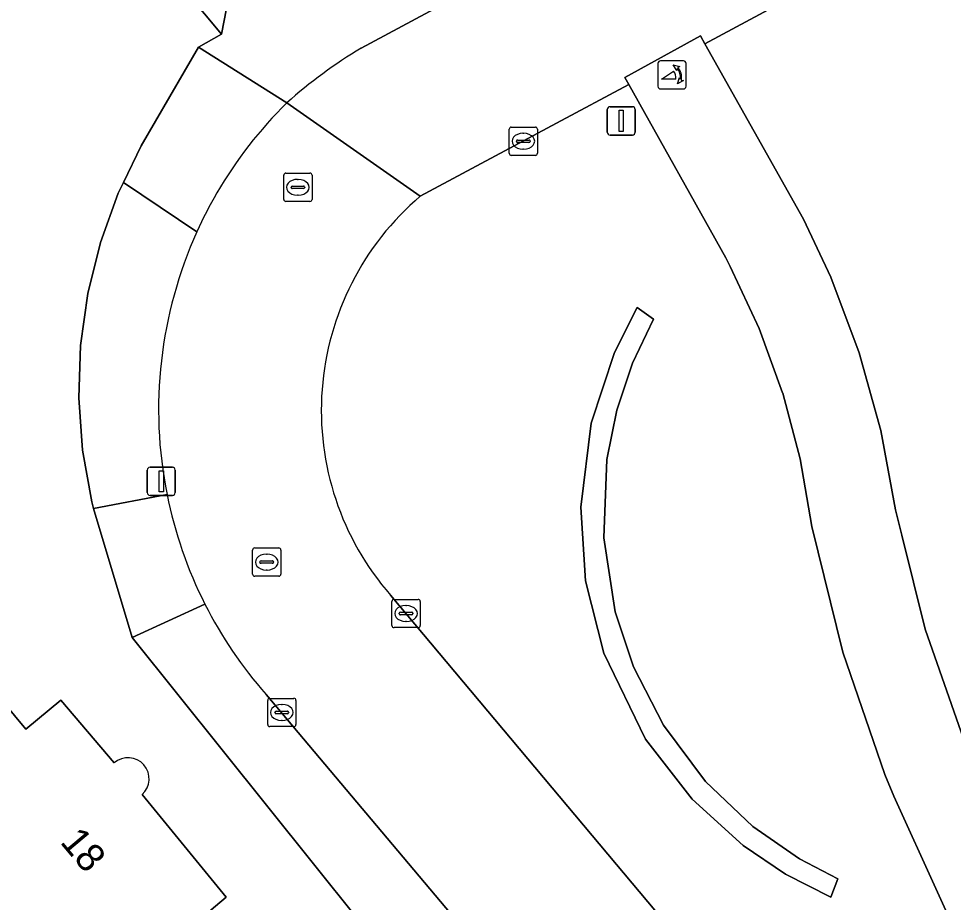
# Model space of a CAD drawing. Extents: x 157320 to 158835, y 386650 to 388491.
# Drawn here: x 157959.22 to 157992.29, y 387030.42 to 387061.67 of the extents above; entities that cross this region are included whole.
import ezdxf

# ---------------------------------------------------------------- set-up
doc = ezdxf.new("R2010")
doc.units = 0
for name, color, linetype in [('IMGEO_Erf', 7, 'Continuous'), ('IMGEO_Fietspad_gesloten', 7, 'Continuous'), ('IMGEO_Groenvoorziening', 7, 'Continuous'), ('IMGEO_Kolk', 7, 'Continuous'), ('IMGEO_Lichtmast', 7, 'Continuous'), ('IMGEO_Pand', 7, 'Continuous'), ('IMGEO_Pand_nummerreeks', 7, 'Continuous'), ('IMGEO_Poller', 7, 'Continuous'), ('IMGEO_Rijbaan_lokaal_gesloten', 7, 'Continuous'), ('IMGEO_Rioolput', 7, 'Continuous'), ('IMGEO_Verkeersbordpaal', 7, 'Continuous'), ('IMGEO_Voetpad_open', 7, 'Continuous')]:
    doc.layers.add(name, color=color, linetype=linetype)

msp = doc.modelspace()

# ---------------------------------------------------------------- linework, layer by layer
at = {"layer": 'IMGEO_Erf'}
for points in [[(157991.12, 387006.005), (157981.864, 387017.312), (157978.709, 387020.934), (157976.019, 387024.066), (157974.987, 387025.267), (157972.834, 387027.804), (157963.229, 387039.777), (157961.86, 387044.345), (157961.804, 387044.578), (157961.479, 387046.406), (157961.346, 387048.258), (157961.408, 387050.114), (157961.663, 387051.953), (157962.109, 387053.755), (157962.741, 387055.501), (157962.924, 387055.878), (157963.552, 387057.171), (157965.583, 387060.657), (157966.396, 387061.12), (157947.439, 387083.778)], [(157966.029, 387021.933), (157957.602, 387014.853), (157953.366, 387019.902), (157958.268, 387024.015), (157952.8, 387030.549), (157947.889, 387026.428), (157943.654, 387031.476), (157951.624, 387038.164), (157955.453, 387041.378), (157959.468, 387036.534), (157960.714, 387037.566), (157962.597, 387035.343)], [(157963.583, 387034.226), (157966.563, 387030.599), (157965.801, 387029.956), (157969.857, 387025.149), (157966.029, 387021.933)]]:
    msp.add_lwpolyline(points, dxfattribs=at)
msp.add_arc((157963.088, 387034.783), 0.745, 311.6564, 131.2146, dxfattribs=at)
at = {"layer": 'IMGEO_Fietspad_gesloten'}
msp.add_lwpolyline([(157992.732, 387035.958), (157991.3, 387040.074), (157990.468, 387043.398), (157990.242, 387044.301), (157989.728, 387047.106), (157988.965, 387049.855), (157987.959, 387052.524), (157986.992, 387054.576), (157983.496, 387060.784), (157983.342, 387061.057), (157980.664, 387059.588), (157980.806, 387059.335), (157984.237, 387053.207), (157984.399, 387052.903), (157985.426, 387050.712), (157986.253, 387048.437), (157986.256, 387048.425), (157986.874, 387046.098), (157987.283, 387043.712), (157988.381, 387039.265), (157989.873, 387034.934), (157990.183, 387034.167), (157994.823, 387023.988)], dxfattribs=at)
at = {"layer": 'IMGEO_Groenvoorziening'}
for points in [[(157948.54, 387084.792), (157947.439, 387083.778), (157966.396, 387061.12), (157966.986, 387064.168)], [(157971.339, 387060.631), (157974.572, 387062.367), (157977.902, 387064.165), (157977.841, 387064.281), (157977.503, 387064.848), (157977.116, 387065.382), (157976.683, 387065.88), (157976.446, 387066.118), (157976.209, 387066.35), (157975.97, 387066.58)], [(157991.21, 387064.929), (157983.496, 387060.784), (157986.992, 387054.576), (157987.959, 387052.524), (157988.965, 387049.855), (157989.728, 387047.106), (157990.242, 387044.301), (157990.468, 387043.398), (157991.3, 387040.074), (157992.732, 387035.958), (157992.911, 387035.516), (157997.623, 387025.234), (157999.152, 387021.817), (158000, 387020.216), (158001.965, 387017.034), (158003.372, 387015.092), (158006.85, 387010.839), (158007.452, 387010.131), (158008.114, 387009.48), (158008.832, 387008.89)], [(157966.986, 387064.168), (157966.396, 387061.12), (157965.583, 387060.657), (157968.704, 387058.691)], [(158004.726, 387008.62), (158000, 387014.593), (157999.477, 387015.254), (157998.198, 387017.21), (157996.359, 387020.524), (157994.823, 387023.988), (157990.183, 387034.167), (157989.873, 387034.934), (157988.381, 387039.265), (157987.283, 387043.712), (157986.874, 387046.098), (157986.256, 387048.425), (157986.253, 387048.437), (157985.426, 387050.712), (157984.399, 387052.903), (157984.237, 387053.207), (157980.806, 387059.335), (157978.256, 387057.971), (157973.431, 387055.39)], [(157965.527, 387054.133), (157962.924, 387055.878), (157962.741, 387055.501), (157962.109, 387053.755), (157961.663, 387051.953), (157961.408, 387050.114), (157961.346, 387048.258), (157961.479, 387046.406), (157961.804, 387044.578), (157961.86, 387044.345), (157964.468, 387044.834)], [(157972.38, 387041.273), (158000, 387008.374), (158007.03, 387000), (158030.213, 386972.386), (158034.557, 386967.207)], [(157965.81, 387040.962), (157963.229, 387039.777), (157972.834, 387027.804), (157974.9, 387029.543), (157967.973, 387037.769)]]:
    msp.add_lwpolyline(points, dxfattribs=at)
for points in [[(157987.96, 387030.601), (157988.208, 387031.247), (157986.851, 387031.955), (157985.204, 387033.095), (157983.524, 387034.685), (157982.032, 387036.676), (157980.974, 387038.739), (157980.33, 387040.686), (157979.925, 387043.301), (157980.031, 387046.082), (157980.381, 387047.819), (157980.94, 387049.489), (157981.68, 387051.035), (157981.107, 387051.459), (157980.301, 387049.864), (157979.481, 387047.366), (157979.108, 387044.395), (157979.281, 387041.788), (157979.925, 387039.224), (157981.4, 387036.186), (157983.047, 387034.059), (157984.853, 387032.422), (157986.359, 387031.411)], [(157980.94, 387049.489), (157980.381, 387047.819), (157980.031, 387046.082), (157979.925, 387043.301), (157980.33, 387040.686), (157980.974, 387038.739), (157982.032, 387036.676), (157983.524, 387034.685), (157985.204, 387033.095), (157986.851, 387031.955), (157988.208, 387031.247), (157987.96, 387030.601), (157986.359, 387031.411), (157984.853, 387032.422), (157983.047, 387034.059), (157981.4, 387036.186), (157979.925, 387039.224), (157979.281, 387041.788), (157979.108, 387044.395), (157979.481, 387047.366), (157980.301, 387049.864), (157981.107, 387051.459), (157981.68, 387051.035)]]:
    msp.add_lwpolyline(points, close=True, dxfattribs=at)
for centre, radius, start, end in [((157980.387, 387045.582), 17.559, 121.0158, 131.7084), ((157979.873, 387047.813), 9.946, 130.3719, 221.1126), ((157979.394, 387047.844), 15.226, 155.6043, 191.4016), ((157979.27, 387047.751), 15.075, 206.7653, 221.4636)]:
    msp.add_arc(centre, radius, start, end, dxfattribs=at)
at = {"layer": 'IMGEO_Kolk'}
for p, q in [((157976.651, 387057.834), (157977.503, 387057.834)), ((157976.576, 387056.908), (157976.576, 387057.76)), ((157977.064, 387057.614), (157977.089, 387057.614)), ((157977.577, 387057.76), (157977.577, 387056.908)), ((157976.835, 387057.328), (157976.835, 387057.34)), ((157977.273, 387057.291), (157976.875, 387057.291)), ((157976.878, 387057.377), (157977.276, 387057.377)), ((157977.319, 387057.34), (157977.319, 387057.328)), ((157977.503, 387056.834), (157976.651, 387056.834)), ((157977.087, 387057.054), (157977.062, 387057.054)), ((157972.426, 387040.204), (157972.426, 387041.056)), ((157972.501, 387041.13), (157973.353, 387041.13)), ((157972.914, 387040.91), (157972.939, 387040.91)), ((157973.427, 387041.056), (157973.427, 387040.204)), ((157972.685, 387040.624), (157972.685, 387040.636)), ((157973.123, 387040.587), (157972.725, 387040.587)), ((157972.728, 387040.673), (157973.126, 387040.673)), ((157973.169, 387040.636), (157973.169, 387040.624)), ((157972.937, 387040.35), (157972.912, 387040.35)), ((157973.353, 387040.13), (157972.501, 387040.13)), ((157968.104, 387037.629), (157968.956, 387037.629)), ((157968.029, 387036.703), (157968.029, 387037.555)), ((157968.517, 387037.409), (157968.542, 387037.409)), ((157969.03, 387037.555), (157969.03, 387036.703)), ((157968.288, 387037.123), (157968.288, 387037.135)), ((157968.726, 387037.086), (157968.328, 387037.086)), ((157968.331, 387037.172), (157968.729, 387037.172)), ((157968.772, 387037.135), (157968.772, 387037.123)), ((157968.956, 387036.629), (157968.104, 387036.629)), ((157968.54, 387036.849), (157968.515, 387036.849))]:
    msp.add_line(p, q, dxfattribs=at)
for points in [[(157976.651, 387057.834), (157977.503, 387057.834)], [(157976.576, 387056.908), (157976.576, 387057.76)], [(157977.577, 387057.76), (157977.577, 387056.908)], [(157977.503, 387056.834), (157976.651, 387056.834)], [(157972.426, 387040.204), (157972.426, 387041.056)], [(157972.501, 387041.13), (157973.353, 387041.13)], [(157973.427, 387041.056), (157973.427, 387040.204)], [(157973.353, 387040.13), (157972.501, 387040.13)], [(157968.104, 387037.629), (157968.956, 387037.629)], [(157968.029, 387036.703), (157968.029, 387037.555)], [(157969.03, 387037.555), (157969.03, 387036.703)], [(157968.956, 387036.629), (157968.104, 387036.629)]]:
    msp.add_lwpolyline(points, dxfattribs=at)
for centre, radius, start, end in [((157976.653, 387057.758), 0.0765, 91.552, 178.448), ((157976.653, 387057.758), 0.0765, 91.552, 178.448), ((157977.501, 387057.758), 0.0765, 1.552, 88.448), ((157977.501, 387057.758), 0.0765, 1.552, 88.448), ((157976.875, 387057.337), 0.0403, 85.8775, 175.7526), ((157976.872, 387057.327), 0.0366, 178.938, 274.7102), ((157977.276, 387057.334), 0.043, 264.8664, 352.4533), ((157977.28, 387057.339), 0.0386, 1.7309, 96.639), ((157976.653, 387056.91), 0.0765, 181.552, 268.448), ((157976.653, 387056.91), 0.0765, 181.552, 268.448), ((157977.501, 387056.91), 0.0765, 271.552, 358.448), ((157977.501, 387056.91), 0.0765, 271.552, 358.448), ((157972.503, 387041.054), 0.0765, 91.552, 178.448), ((157972.503, 387041.054), 0.0765, 91.552, 178.448), ((157973.351, 387041.054), 0.0765, 1.552, 88.448), ((157973.351, 387041.054), 0.0765, 1.552, 88.448), ((157972.725, 387040.633), 0.0403, 85.8775, 175.7526), ((157972.722, 387040.623), 0.0366, 178.938, 274.7102), ((157973.126, 387040.63), 0.043, 264.8664, 352.4533), ((157973.13, 387040.635), 0.0386, 1.7309, 96.639), ((157972.503, 387040.206), 0.0765, 181.552, 268.448), ((157972.503, 387040.206), 0.0765, 181.552, 268.448), ((157973.351, 387040.206), 0.0765, 271.552, 358.448), ((157973.351, 387040.206), 0.0765, 271.552, 358.448), ((157968.106, 387037.553), 0.0765, 91.552, 178.448), ((157968.106, 387037.553), 0.0765, 91.552, 178.448), ((157968.954, 387037.553), 0.0765, 1.552, 88.448), ((157968.954, 387037.553), 0.0765, 1.552, 88.448), ((157968.328, 387037.132), 0.0403, 85.8775, 175.7526), ((157968.325, 387037.122), 0.0366, 178.938, 274.7102), ((157968.729, 387037.129), 0.043, 264.8664, 352.4533), ((157968.733, 387037.134), 0.0386, 1.7309, 96.639), ((157968.106, 387036.705), 0.0765, 181.552, 268.448), ((157968.106, 387036.705), 0.0765, 181.552, 268.448), ((157968.954, 387036.705), 0.0765, 271.552, 358.448), ((157968.954, 387036.705), 0.0765, 271.552, 358.448)]:
    msp.add_arc(centre, radius, start, end, dxfattribs=at)
for centre, major_axis, ratio, start_param, end_param in [((157977.063, 387057.334), (-0.387, 0.002), 0.722429, 4.712389, 7.853982), ((157977.088, 387057.334), (-0.39, 0.002), 0.717154, 1.570796, 4.712389), ((157972.913, 387040.63), (-0.387, 0.002), 0.722429, 4.712389, 7.853982), ((157972.938, 387040.63), (-0.39, 0.002), 0.717154, 1.570796, 4.712389), ((157968.516, 387037.129), (-0.387, 0.002), 0.722429, 4.712389, 7.853982), ((157968.541, 387037.129), (-0.39, 0.002), 0.717154, 1.570796, 4.712389)]:
    msp.add_ellipse(centre, major_axis=major_axis, ratio=ratio, start_param=start_param, end_param=end_param, dxfattribs=at)
at = {"layer": 'IMGEO_Lichtmast'}
for p, q in [((157963.767, 387044.905), (157963.767, 387045.705)), ((157963.767, 387045.705), (157963.767, 387044.905)), ((157963.867, 387045.805), (157964.657, 387045.805)), ((157964.657, 387045.805), (157963.867, 387045.805)), ((157964.757, 387045.705), (157964.757, 387044.905)), ((157964.757, 387044.905), (157964.757, 387045.705)), ((157964.657, 387044.805), (157963.867, 387044.805)), ((157963.867, 387044.805), (157964.657, 387044.805))]:
    msp.add_line(p, q, dxfattribs=at)
msp.add_lwpolyline([(157964.187, 387045.68), (157964.337, 387045.68), (157964.337, 387044.93), (157964.187, 387044.93), (157964.187, 387045.68)], dxfattribs=at)
for centre, start, end in [((157963.867, 387045.705), 90, 180), ((157963.867, 387045.705), 90, 180), ((157964.657, 387045.705), 0, 90), ((157964.657, 387045.705), 360, 90), ((157963.867, 387044.905), 180, 270), ((157963.867, 387044.905), 180, 270), ((157964.657, 387044.905), 270, 0), ((157964.657, 387044.905), 270, 0)]:
    msp.add_arc(centre, 0.1, start, end, dxfattribs=at)
at = {"layer": 'IMGEO_Pand'}
msp.add_lwpolyline([(157962.597, 387035.343), (157960.714, 387037.566), (157959.468, 387036.534), (157955.453, 387041.378), (157951.624, 387038.164), (157943.654, 387031.476), (157947.889, 387026.428), (157952.8, 387030.549), (157958.268, 387024.015), (157953.366, 387019.902), (157957.602, 387014.853), (157966.029, 387021.933), (157969.857, 387025.149), (157965.801, 387029.956), (157966.563, 387030.599), (157963.583, 387034.226)], dxfattribs=at)
msp.add_arc((157963.088, 387034.783), 0.745, 311.6564, 131.2146, dxfattribs=at)
at = {"layer": 'IMGEO_Poller'}
for p, q in [((157982.742, 387060.179), (157981.934, 387060.179)), ((157982.742, 387060.179), (157981.934, 387060.179)), ((157981.84, 387060.084), (157981.84, 387059.277)), ((157981.84, 387060.084), (157981.84, 387059.277)), ((157982.836, 387059.277), (157982.836, 387060.084)), ((157982.836, 387059.277), (157982.836, 387060.084)), ((157981.934, 387059.182), (157982.742, 387059.182)), ((157981.934, 387059.182), (157982.742, 387059.182))]:
    msp.add_line(p, q, dxfattribs=at)
for points in [[(157982.475, 387059.535), (157981.962, 387059.535), (157982.392, 387059.81)], [(157982.519, 387059.908), (157982.507, 387059.835), (157982.382, 387060.04)], [(157982.382, 387060.04), (157982.613, 387059.974), (157982.542, 387059.942)], [(157982.535, 387059.363), (157982.601, 387059.594), (157982.631, 387059.526)], [(157982.667, 387059.499), (157982.739, 387059.488), (157982.535, 387059.363)]]:
    msp.add_lwpolyline(points, dxfattribs=at)
for centre, radius, start, end in [((157981.934, 387060.084), 0.0946, 90, 180), ((157981.934, 387060.084), 0.0946, 90, 180), ((157982.742, 387060.084), 0.0946, 0, 90), ((157982.742, 387060.084), 0.0946, 0, 90), ((157982.147, 387059.585), 0.332, 351.3247, 42.4854), ((157982.161, 387059.595), 0.476, 351.7527, 41.1691), ((157982.161, 387059.595), 0.516, 349.3569, 42.2912), ((157981.934, 387059.277), 0.0946, 180, 270), ((157981.934, 387059.277), 0.0946, 180, 270), ((157982.742, 387059.277), 0.0946, 270, 0), ((157982.742, 387059.277), 0.0946, 270, 0)]:
    msp.add_arc(centre, radius, start, end, dxfattribs=at)
at = {"layer": 'IMGEO_Rijbaan_lokaal_gesloten'}
for points in [[(158069.112, 387113.407), (158053.278, 387104.849), (158048.471, 387102.262), (158043.652, 387099.663), (158042.727, 387099.157), (158031.216, 387092.927), (158027.751, 387091.073), (158006.853, 387079.818), (158003.296, 387077.92), (158000, 387076.136), (157981.742, 387066.255), (157981.633, 387066.187), (157980.61, 387065.638), (157980.781, 387065.373), (157978.031, 387063.902), (157977.968, 387064.034), (157977.902, 387064.165), (157974.572, 387062.367), (157971.339, 387060.631)], [(157968.704, 387058.691), (157973.431, 387055.39), (157978.256, 387057.971), (157980.806, 387059.335), (157980.664, 387059.588), (157983.342, 387061.057), (157983.496, 387060.784), (157991.21, 387064.929), (157992.396, 387065.574), (158000, 387069.676), (158001.636, 387070.559), (158020.488, 387080.731), (158024.905, 387083.087), (158046.373, 387094.699), (158049.829, 387096.568), (158051.968, 387097.719), (158061.394, 387102.79)], [(157973.431, 387055.39), (157968.704, 387058.691)], [(158073.076, 386921.282), (158041.42, 386959.024), (158034.557, 386967.207), (158030.213, 386972.386), (158007.03, 387000), (158000, 387008.374), (157972.38, 387041.273)], [(157967.973, 387037.769), (157974.9, 387029.543), (157977.042, 387026.998), (157978.062, 387025.786), (157980.721, 387022.628), (157983.795, 387018.928), (157993.128, 387007.669), (157996.153, 387004.218), (157999.697, 387000), (158000, 386999.639), (158002.787, 386996.322), (158003.5, 386995.491), (158020.47, 386975.229), (158025.301, 386969.475), (158035.357, 386957.488), (158038.597, 386953.625), (158042.903, 386948.477), (158045.801, 386945.052), (158050.997, 386938.872), (158051.663, 386938.08), (158063.817, 386923.608), (158065.16, 386922.009), (158067.446, 386919.287)]]:
    msp.add_lwpolyline(points, dxfattribs=at)
for centre, radius, start, end in [((157980.387, 387045.582), 17.559, 121.0158, 131.7084), ((157979.374, 387047.87), 15.197, 134.6, 149.847), ((157979.151, 387047.975), 14.951, 149.7635, 155.6778), ((157979.873, 387047.813), 9.946, 130.3719, 221.1126), ((157979.394, 387047.844), 15.226, 155.6043, 191.4016), ((157979.393, 387047.838), 15.224, 191.3811, 206.8506), ((157979.27, 387047.751), 15.075, 206.7653, 221.4636)]:
    msp.add_arc(centre, radius, start, end, dxfattribs=at)
at = {"layer": 'IMGEO_Rioolput'}
for p, q in [((157968.597, 387055.279), (157968.597, 387056.131)), ((157968.672, 387056.205), (157969.524, 387056.205)), ((157969.598, 387056.131), (157969.598, 387055.279)), ((157969.085, 387055.985), (157969.11, 387055.985)), ((157968.856, 387055.699), (157968.856, 387055.711)), ((157969.294, 387055.662), (157968.896, 387055.662)), ((157968.899, 387055.748), (157969.297, 387055.748)), ((157969.34, 387055.711), (157969.34, 387055.699)), ((157969.524, 387055.205), (157968.672, 387055.205)), ((157969.108, 387055.425), (157969.083, 387055.425)), ((157967.57, 387042.948), (157968.422, 387042.948)), ((157967.495, 387042.022), (157967.495, 387042.874)), ((157967.983, 387042.728), (157968.008, 387042.728)), ((157968.496, 387042.874), (157968.496, 387042.022)), ((157967.754, 387042.442), (157967.754, 387042.454)), ((157968.192, 387042.405), (157967.794, 387042.405)), ((157967.797, 387042.491), (157968.195, 387042.491)), ((157968.238, 387042.454), (157968.238, 387042.442)), ((157968.422, 387041.948), (157967.57, 387041.948)), ((157968.006, 387042.168), (157967.981, 387042.168))]:
    msp.add_line(p, q, dxfattribs=at)
for points in [[(157968.597, 387055.279), (157968.597, 387056.131)], [(157968.672, 387056.205), (157969.524, 387056.205)], [(157969.598, 387056.131), (157969.598, 387055.279)], [(157969.524, 387055.205), (157968.672, 387055.205)], [(157967.57, 387042.948), (157968.422, 387042.948)], [(157967.495, 387042.022), (157967.495, 387042.874)], [(157968.496, 387042.874), (157968.496, 387042.022)], [(157968.422, 387041.948), (157967.57, 387041.948)]]:
    msp.add_lwpolyline(points, dxfattribs=at)
for centre, radius, start, end in [((157968.674, 387056.129), 0.0765, 91.552, 178.448), ((157968.674, 387056.129), 0.0765, 91.552, 178.448), ((157969.522, 387056.129), 0.0765, 1.552, 88.448), ((157969.522, 387056.129), 0.0765, 1.552, 88.448), ((157968.896, 387055.708), 0.0403, 85.8775, 175.7526), ((157968.893, 387055.698), 0.0366, 178.938, 274.7102), ((157969.297, 387055.705), 0.043, 264.8664, 352.4533), ((157969.301, 387055.71), 0.0386, 1.7309, 96.639), ((157968.674, 387055.281), 0.0765, 181.552, 268.448), ((157968.674, 387055.281), 0.0765, 181.552, 268.448), ((157969.522, 387055.281), 0.0765, 271.552, 358.448), ((157969.522, 387055.281), 0.0765, 271.552, 358.448), ((157967.572, 387042.872), 0.0765, 91.552, 178.448), ((157967.572, 387042.872), 0.0765, 91.552, 178.448), ((157968.42, 387042.872), 0.0765, 1.552, 88.448), ((157968.42, 387042.872), 0.0765, 1.552, 88.448), ((157967.794, 387042.451), 0.0403, 85.8775, 175.7526), ((157967.791, 387042.441), 0.0366, 178.938, 274.7102), ((157968.195, 387042.448), 0.043, 264.8664, 352.4533), ((157968.199, 387042.453), 0.0386, 1.7309, 96.639), ((157967.572, 387042.024), 0.0765, 181.552, 268.448), ((157967.572, 387042.024), 0.0765, 181.552, 268.448), ((157968.42, 387042.024), 0.0765, 271.552, 358.448), ((157968.42, 387042.024), 0.0765, 271.552, 358.448)]:
    msp.add_arc(centre, radius, start, end, dxfattribs=at)
for centre, major_axis, ratio, start_param, end_param in [((157969.084, 387055.705), (-0.387, 0.002), 0.722429, 4.712389, 7.853982), ((157969.109, 387055.705), (-0.39, 0.002), 0.717154, 1.570796, 4.712389), ((157967.982, 387042.448), (-0.387, 0.002), 0.722429, 4.712389, 7.853982), ((157968.007, 387042.448), (-0.39, 0.002), 0.717154, 1.570796, 4.712389)]:
    msp.add_ellipse(centre, major_axis=major_axis, ratio=ratio, start_param=start_param, end_param=end_param, dxfattribs=at)
at = {"layer": 'IMGEO_Verkeersbordpaal'}
for p, q in [((157980.045, 387057.654), (157980.045, 387058.454)), ((157980.045, 387058.454), (157980.045, 387057.654)), ((157980.145, 387058.554), (157980.935, 387058.554)), ((157980.935, 387058.554), (157980.145, 387058.554)), ((157981.035, 387058.454), (157981.035, 387057.654)), ((157981.035, 387057.654), (157981.035, 387058.454)), ((157980.935, 387057.554), (157980.145, 387057.554)), ((157980.145, 387057.554), (157980.935, 387057.554))]:
    msp.add_line(p, q, dxfattribs=at)
msp.add_lwpolyline([(157980.465, 387058.429), (157980.615, 387058.429), (157980.615, 387057.679), (157980.465, 387057.679), (157980.465, 387058.429)], dxfattribs=at)
for centre, start, end in [((157980.145, 387058.454), 90, 180), ((157980.145, 387058.454), 90, 180), ((157980.935, 387058.454), 0, 90), ((157980.935, 387058.454), 360, 90), ((157980.145, 387057.654), 180, 270), ((157980.145, 387057.654), 180, 270), ((157980.935, 387057.654), 270, 0), ((157980.935, 387057.654), 270, 0)]:
    msp.add_arc(centre, 0.1, start, end, dxfattribs=at)
at = {"layer": 'IMGEO_Voetpad_open'}
for points in [[(157968.704, 387058.691), (157965.583, 387060.657), (157963.552, 387057.171), (157962.924, 387055.878), (157965.527, 387054.133)], [(157964.468, 387044.834), (157961.86, 387044.345), (157963.229, 387039.777), (157965.81, 387040.962)]]:
    msp.add_lwpolyline(points, dxfattribs=at)
for centre, radius, start, end in [((157979.374, 387047.87), 15.197, 134.6, 149.847), ((157979.151, 387047.975), 14.951, 149.7635, 155.6778), ((157979.393, 387047.838), 15.224, 191.3811, 206.8506)]:
    msp.add_arc(centre, radius, start, end, dxfattribs=at)

# ---------------------------------------------------------------- texts
at = {"layer": 'IMGEO_Pand_nummerreeks'}
msp.add_text('18', height=1, rotation=310.0152, dxfattribs=at).set_placement((157960.655, 387032.535))

doc.saveas('drawing.dxf')
